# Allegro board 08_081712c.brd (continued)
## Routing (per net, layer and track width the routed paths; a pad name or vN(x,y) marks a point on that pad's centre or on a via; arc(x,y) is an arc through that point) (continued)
JTAG_EMU*: length 28
  TOP w0.14: R475.2 v1(206.36,16.31)
  L3_SIG w0.114: v1(190.25,32.07) 191.39,30.92 195.58,30.92 203.07,23.43 203.07,20.51 204.34,19.24 204.98,19.24 205.31,18.91 v2(206.65,18.91)
  BOTTOM w0.14: v2(206.65,18.91) 206.65,16.59 v1(206.36,16.31) ; R500.1 v1(190.25,32.07)
JTAG_EMU_CONN*: length 27.1
  TOP w0.14: R488.2 S11.8 195.71,58.61 194.94,57.85 194.94,57.12 195.71,56.36 195.71,54.67 193.04,52.01 193.04,45.15 189.99,42.1 189.99,40.45 v1(190.37,40.07)
  BOTTOM w0.14: v1(190.37,40.07) 190.88,40.07 191.27,39.68 U60.11
JTAG_EN: length 61.5
  TOP w0.14: U58.14 U58.15 213.38,36.24 212.98,36.64 212.28,36.64 R496.1 v1(210.47,37.46)
  TOP w0.203: v1(220.47,20.38) 220.16,20.69 U59.2
  L3_SIG w0.114: v1(193.04,40.32) 207.14,40.32 209.99,37.46 v1(210.47,37.46)
  L8_SIG w0.114: v1(220.47,20.38) 220.01,19.93 218.14,19.93 215.58,22.48 213.35,22.48 210.16,19.29 209.63,19.29 209.42,19.49 209.42,19.72 209.15,20 208.76,20 v2(208.64,20.11)
  BOTTOM w0.114: U60.15 193.27,40.09 v1(193.04,40.32)
  BOTTOM w0.127: v2(208.64,20.11) 208.64,21.7 209.35,22.4 209.35,24.19 209.67,24.51 210.81,24.51 211.82,25.53 211.82,36.11 v1(210.47,37.46)
  BOTTOM w0.14: v1(193.04,40.32) 192.77,40.06 U60.14
JTAG_IO: length 10
  TOP w0.203: C368.1 211.72,34.6 U58.16 ; C366.1 220.44,23.94 220.16,23.66 U59.6
  TOP w0.508: C366.1 v1(220.48,24.8) ; P10.2 v1(227.21,21.65) ; R488.1 v1(195.71,64.08) ; C368.1 v1(210.67,34.87) ; R490.1 v1(198.25,47.56)
  BOTTOM w0.203: C365.1 194.93,38.03 U60.16
  BOTTOM w0.508: C365.1 v1(195.91,38.3)
JTAG_PD: length 24.4
  L3_SIG w0.114: v2(209.05,20.51) 208.66,20.89 208.24,20.89 207.1,19.75 204.6,19.75 203.83,20.51 203.83,23.43 194.82,32.45 193.67,32.45 v1(193.29,32.07)
  BOTTOM w0.14: R501.1 v1(193.29,32.07)
JTAG_PD_CONN: length 27
  TOP w0.14: v1(192.27,40.96) 194.18,42.86 209.55,42.86 213.49,46.8 R489.2
  BOTTOM w0.14: U60.13 v1(192.27,40.96)
JTAG_SOM_ROUTE: length 21.4
  TOP w0.127: U15.1 232.29,83.41 230.12,85.58 S2.2 230.12,95.85 232.28,98.02 U14.1
JTAG_SPI_CS_N: length 5.9
  L8_SIG w0.114: v2(207.05,18.91) 206.77,18.64 205.73,18.64 205.17,19.2 205.17,19.45 206.63,20.91 206.63,21.69 v2(207.05,22.11)
JTAG_TARGET_RESET_N: length 14.5
  TOP w0.203: U59.9 v1(217.93,21.91) ; U59.8 218.67,22.31 v1(218.31,22.67)
  L8_SIG w0.114: v1(218.31,22.67) 218.31,22.29 v1(217.93,21.91) 216.6,23.24 212.21,23.24 209.2,20.24 208.93,20.24 208.66,20.51 v2(208.24,20.51)
JTAG_TARGET_RESET_N_CONN: length 45.4
  TOP w0.14: S11.10 v1(198.25,50.16) R490.2 R491.1
  TOP w0.203: U59.4 v1(222,21.91) ; U59.5 221.38,22.31 v1(221.74,22.67)
  L3_SIG w0.114: v1(221.74,22.67) 221.74,22.16 v1(222,21.91)
  BOTTOM w0.127: v1(221.74,22.67) 219.96,24.45 219.96,31.78 212.39,39.34 209.06,39.34 v1(198.25,50.16)
JTAG_TARGET_RESET_SOM_A*: length 98.1
  TOP w0.127: SOMA.146 v1(150.39,74.95)
  TOP w0.14: U15.6 v1(233.32,80.91)
  L8_SIG w0.127: v1(163.04,71.2) 163.04,72.24 161.04,74.24 150.67,74.24 150.39,74.52 v1(150.39,74.95)
  BOTTOM w0.127: v1(163.04,71.2) 164.59,72.75 194,72.75 196.9,75.64 196.9,78.97 198.88,80.95 211,80.95 215.26,85.22 229.54,85.22 233.32,81.43 v1(233.32,80.91)
JTAG_TARGET_RESET_SOM_B*: length 50.2
  TOP w0.127: SOMB.146 v1(277.39,74.95)
  TOP w0.14: v1(235.81,80.92) 235.33,81.41 U15.5
  BOTTOM w0.127: v1(277.39,74.95) 274.1,71.65 262.46,71.65 261.04,73.08 249.2,73.08 240.49,81.79 238.38,81.79 237.52,80.92 v1(235.81,80.92)
JTAG_TCK: length 23.8
  TOP w0.14: R474.2 v1(205.49,27.67) ; v1(214.88,31.31) U58.5
  L8_SIG w0.114: v2(206.65,19.31) 206.65,19.72 208.41,21.49 208.41,22.77 205.49,25.7 v1(205.49,27.67) 207.53,29.72 213.29,29.72 v1(214.88,31.31)
JTAG_TCK_CONN: length 24.2
  TOP w0.14: S11.13 v1(205.87,50.03)
  TOP w0.203: R494.2 v1(214.38,40.12)
  L8_SIG w0.14: v1(214.38,40.12) 213.53,39.27 211.11,39.27 205.87,44.51 205.87,46.5 205.62,46.75 204.46,46.75 204.22,46.99 204.22,47.34 204.46,47.58 205.62,47.58 205.87,47.83 205.87,48.18 205.62,48.42 204.46,48.42 204.22,48.67 204.22,49.01 204.46,49.26 205.62,49.26 205.87,49.51 v1(205.87,50.03)
JTAG_TCK_SOM_A: length 103
  TOP w0.127: SOMA.138 v1(148.39,74.95)
  TOP w0.14: U14.13 237.79,96.52 v1(237.31,96.99) ; U9.5 v1(202.73,86.73)
  L8_SIG w0.127: v1(202.73,86.73) 193.65,77.65 154.77,77.65 153.54,76.43 149.26,76.43 148.46,75.63 148.46,75.59 148.39,75.52 v1(148.39,74.95)
  BOTTOM w0.127: v1(237.31,96.99) 236.44,96.99 234.44,95 234.44,94.36 233.93,93.85 211.94,93.85 206.22,88.14 204.14,88.14 v1(202.73,86.73)
JTAG_TCK_SOM_B: length 93.8
  TOP w0.127: SOMB.138 v1(275.39,75.71)
  TOP w0.14: U14.14 239.05,97.02 v1(239.45,96.62) ; U9.6 v1(205.54,86.08)
  BOTTOM w0.127: v1(205.54,86.08) 206.38,86.92 206.38,87.5 212.09,93.22 233.93,93.22 234.95,94.23 234.95,95 236.44,96.49 237.74,96.49 238.09,96.14 238.96,96.14 v1(239.45,96.62) 240.56,96.62 251.36,85.83 256.67,85.83 261.85,80.65 261.85,75.08 263.4,73.53 271.98,73.53 274.16,75.71 v1(275.39,75.71)
JTAG_TDI: length 22.7
  TOP w0.14: U58.6 215.38,31.95 v1(215.77,31.56)
  L8_SIG w0.114: v2(207.84,20.11) 207.84,20.5 209.17,21.82 209.17,22.5 206.22,25.44 206.22,27.66 207.52,28.96 214.12,28.96 215.77,30.61 v1(215.77,31.56)
JTAG_TDI_CONN: length 24
  TOP w0.14: S11.11 v1(200.79,50.03)
  TOP w0.203: R493.2 v1(215.9,40.12)
  L8_SIG w0.14: v1(215.9,40.12) 213.95,38.16 210.95,38.16 200.79,48.32 v1(200.79,50.03)
JTAG_TDI_SOM_A: length 107.1
  TOP w0.127: SOMA.142 v1(149.39,74.95)
  TOP w0.14: U14.10 v1(239.3,95.02)
  L8_SIG w0.127: v1(162.05,72.03) 160.47,73.61 150.16,73.61 149.39,74.38 v1(149.39,74.95)
  BOTTOM w0.127: v1(162.05,72.03) 163.86,73.84 175.52,73.84 178.77,77.09 184.33,77.09 186.66,74.75 192.66,74.75 194.31,76.4 194.31,79.63 198.68,84 204.77,84 209.96,89.18 233.46,89.18 v1(239.3,95.02)
JTAG_TDI_SOM_B: length 55
  TOP w0.127: SOMB.142 v1(276.39,75.71)
  TOP w0.14: U52.7 v1(235.78,87.52)
  BOTTOM w0.127: v1(235.78,87.52) 236.84,86.46 241.43,86.46 242.75,85.14 256.57,85.14 260.99,80.72 260.99,74.8 263.14,72.64 273.85,72.64 276.39,75.19 v1(276.39,75.71)
JTAG_TDI_SOM_B_Z: length 19.4
  TOP w0.127: U52.6 236.03,88.02 237.69,86.36 240.92,86.36 243.05,88.49 243.05,91.97 239.51,95.52 U14.11
JTAG_TDI_TDO_SOM_B: length 3
  TOP w0.127: U52.2 234.07,90.02 233.94,89.9 233.94,88.67 234.09,88.52 U52.5
JTAG_TDO: length 24.6
  L3_SIG w0.114: v1(191.77,32.07) 191.77,33.21 192.34,33.78 192.34,34.34 192.51,34.5 192.75,34.5 192.91,34.34 192.91,33.78 193.08,33.61 193.32,33.61 193.48,33.78 193.48,34.34 193.65,34.5 193.89,34.5 194.06,34.34 194.06,33.78 194.25,33.59 194.69,33.59 204.6,23.69 204.6,22.67 205.56,21.71 v2(205.84,21.71)
  BOTTOM w0.14: R499.1 v1(191.77,32.07)
JTAG_TDO_CONN: length 27.1
  TOP w0.14: S11.12 203.33,49.34 204.22,48.45 205.23,48.45 205.99,47.69 205.99,44.89 205.23,44.13 193.67,44.13 191.26,41.72 v1(191.26,40.7)
  BOTTOM w0.14: U60.12 191.77,39.76 191.77,39.77 191.77,40.2 v1(191.26,40.7)
JTAG_TDO_SOM_A: length 103.6
  TOP w0.127: SOMA.140 v1(148.9,75.45)
  TOP w0.14: U52.4 v1(235.65,89.02)
  L8_SIG w0.127: v1(148.9,75.45) 148.9,74.17 149.96,73.11 160.15,73.11 v1(162.05,71.2)
  BOTTOM w0.127: v1(235.65,89.02) 234.77,88.14 224.79,88.14 224.15,88.77 210.31,88.77 204.98,83.44 199.29,83.44 195.07,79.22 195.07,76.25 193.14,74.32 186.13,74.32 183.9,76.56 179.1,76.56 175.82,73.28 164.13,73.28 v1(162.05,71.2)
JTAG_TDO_SOM_A_Z: length 20.8
  TOP w0.127: U14.6 235.98,95.52 236.4,95.1 236.4,93.73 236.75,93.37 240.26,93.37 242.29,91.34 242.29,89.2 241.11,88.02 U52.11 237.74,88.02 236.24,89.52 U52.3
JTAG_TDO_SOM_B: length 51.2
  TOP w0.127: SOMB.140 v1(275.9,76.22)
  TOP w0.14: U52.9 v1(239.43,87.02)
  BOTTOM w0.127: v1(239.43,87.02) 241.26,87.02 242.86,85.42 256.68,85.42 261.39,80.71 261.39,74.9 263.3,73 273.41,73 275.9,75.49 v1(275.9,76.22)
JTAG_TDO_SOM_B_Z: length 18
  TOP w0.127: U52.10 241.32,87.52 242.65,88.85 242.65,91.54 240.54,93.65 237.08,93.65 236.85,93.88 236.85,95.25 236.09,96.02 U14.5
JTAG_TMS: length 22.9
  TOP w0.14: U58.4 214.38,32.2 v1(213.99,31.81)
  L8_SIG w0.114: v2(205.84,22.11) 206.25,22.51 206.25,23.18 204.72,24.7 204.72,27.94 208.6,31.81 210.66,31.81 210.86,31.61 210.86,30.78 211.06,30.58 211.35,30.58 211.55,30.78 211.55,31.61 211.75,31.81 212.03,31.81 212.23,31.61 212.23,30.78 212.43,30.58 212.72,30.58 212.92,30.78 212.92,31.61 213.12,31.81 v1(213.99,31.81)
JTAG_TMS_CONN: length 24.2
  TOP w0.14: S11.14 v1(208.41,50.03)
  TOP w0.203: R492.2 v1(212.85,40.12)
  L8_SIG w0.14: v1(208.41,50.03) 208.41,49.32 208.16,49.07 207.26,49.07 207.01,48.83 207.01,48.48 207.26,48.24 209.43,48.24 209.68,47.99 209.68,47.64 209.43,47.4 207.26,47.4 207.01,47.15 207.01,46.81 207.26,46.56 209.43,46.56 209.68,46.31 209.68,45.97 209.43,45.72 208.4,45.72 208.15,45.48 208.15,43.62 211.66,40.12 v1(212.85,40.12)
JTAG_TMS_SOM_A: length 102
  TOP w0.127: SOMA.136 v1(147.9,75.45)
  TOP w0.14: U9.2 203.11,88.68 v1(202.82,88.39) ; U14.3 v1(235.78,97.02)
  L8_SIG w0.127: v1(202.82,88.39) 202.82,87.63 193.29,78.1 154.48,78.1 153.16,76.78 148.69,76.78 147.9,75.99 v1(147.9,75.45)
  BOTTOM w0.127: v1(202.82,88.39) 203.11,88.68 205.97,88.68 211.69,94.4 232.48,94.4 235.09,97.02 v1(235.78,97.02)
JTAG_TMS_SOM_B: length 97
  TOP w0.127: SOMB.136 v1(274.9,76.22)
  TOP w0.14: U9.3 203.22,88.03 202.95,87.76 v1(202.13,87.76) ; U14.2 v1(233.77,97.52)
  BOTTOM w0.127: v1(202.13,87.76) 202.13,88.62 202.79,89.28 205.79,89.28 211.58,95.07 231.33,95.07 v1(233.77,97.52) 240.69,97.52 251.92,86.28 256.61,86.28 262.31,80.59 262.31,75.13 263.47,73.96 271.75,73.96 274.01,76.22 v1(274.9,76.22)
JTAG_TRST_N: length 22.7
  TOP w0.14: v1(216.41,31.94) 215.88,32.47 U58.7
  L8_SIG w0.114: v1(216.41,31.94) 216.41,31.24 216.61,31.04 217.73,31.04 217.93,30.84 217.93,30.56 217.73,30.36 216.61,30.36 216.41,30.16 216.41,25.59 215.9,25.08 209.23,25.08 208.91,24.76 208.91,24.07 209.93,23.05 209.93,21.8 v2(209.05,20.91)
JTAG_TRST_N_CONN: length 24.1
  TOP w0.14: S11.15 v1(210.95,50.03)
  TOP w0.203: R495.2 v1(217.42,40.12)
  L8_SIG w0.14: v1(210.95,50.03) 210.95,49.28 211.19,49.03 212.1,49.03 212.34,48.79 212.34,48.44 212.1,48.19 211.19,48.19 210.95,47.95 210.95,47.6 211.19,47.35 212.1,47.35 212.34,47.11 212.34,46.76 212.1,46.52 211.19,46.52 210.95,46.27 210.95,45.92 211.19,45.68 212.1,45.68 212.34,45.43 212.34,45.09 212.1,44.84 211.19,44.84 210.95,44.59 210.95,42.1 211.96,41.08 216.46,41.08 v1(217.42,40.12)
JTAG_TRST_SOM_A*: length 96.8
  TOP w0.127: SOMA.144 v1(149.9,75.45)
  TOP w0.14: U15.3 v1(235.78,82.41) ; U9.9 v1(208.58,86.08)
  L8_SIG w0.127: v1(149.9,75.45) 150.49,76.05 153.75,76.05 154.79,77.09 193.62,77.09 200.99,84.45 206.96,84.45 v1(208.58,86.08)
  BOTTOM w0.127: v1(208.58,86.08) 212.19,86.08 213.11,86.99 230.63,86.99 235.22,82.41 v1(235.78,82.41)
JTAG_TRST_SOM_B*: length 79.9
  TOP w0.127: SOMB.144 v1(276.9,76.22)
  TOP w0.14: U9.8 v1(211.29,85.43) ; U15.2 v1(233.77,82.91)
  BOTTOM w0.127: v1(276.9,76.22) 276.9,75.14 273.89,72.14 262.76,72.14 261.37,73.53 249.48,73.53 240.63,82.38 237.19,82.38 236.69,81.88 234.8,81.88 v1(233.77,82.91) 230.1,86.59 213.79,86.59 212.63,85.43 v1(211.29,85.43)
JTG0_TARGET_RESET*: length 53.2
  TOP w0.127: v1(206.76,73.86) 209.67,73.86 216.22,80.41 U15.7
  TOP w0.14: S11.7 v1(198.25,61.47) 200.46,63.69 R532.1 ; R583.2 v1(206.76,73.86)
  BOTTOM w0.14: v1(198.25,61.47) 198.25,65.35 v1(206.76,73.86)
JTG0_TCK/SWCLK_LOCAL: length 89.4
  TOP w0.14: S11.4 v1(205.87,61.47) 206.5,62.11 P8.4 ; U14.12 v1(237.55,96.02)
  L8_SIG w0.127: v1(205.87,61.47) 204.34,61.47 203.93,61.07 203.93,60.48 204.44,59.97 208.48,59.97 214.3,65.79 214.3,73.97 216.74,76.41 216.74,79.46 219.79,82.5 219.79,88.27 226.77,95.25 234.57,95.25 235.35,94.47 236.01,94.47 237.55,96.01 v1(237.55,96.02)
  BOTTOM w0.14: P35.4 211.24,76.38 211.24,65.73 207.93,62.42 206.81,62.42 v1(205.87,61.47)
JTG0_TDI_LOCAL: length 95.6
  TOP w0.14: U14.9 v1(237.55,94.52) ; S11.6 v1(200.79,61.47) 201.73,62.42 203.07,62.42 203.96,63.31 P8.8
  L8_SIG w0.127: v1(237.55,94.52) 236.91,93.88 225.95,93.88 220.14,88.07 220.14,82.36 217.09,79.31 217.09,76.27 214.66,73.83 214.66,65.41 208.73,59.49 202.77,59.49 v1(200.79,61.47)
  BOTTOM w0.14: P35.8 210.13,74.96 210.13,66.3 207.64,63.82 203.13,63.82 v1(200.79,61.47)
JTG0_TDO_LOCAL: length 91.8
  TOP w0.14: P8.6 205.23,63.38 v1(203.33,61.47) S11.5 ; U14.7 v1(235.78,95.02)
  L8_SIG w0.127: v1(203.33,61.47) 203.33,62.61 203.71,62.99 204.47,62.99 204.65,62.81 204.65,62.42 204.84,62.23 205.1,62.23 205.29,62.42 205.29,62.81 205.47,62.99 206.38,62.99 206.76,62.61 206.76,60.94 207.24,60.45 208.25,60.45 213.94,66.15 213.94,74.12 216.38,76.56 216.38,79.6 219.43,82.65 219.43,88.42 226.87,95.86 234.94,95.86 v1(235.78,95.02)
  BOTTOM w0.14: P35.6 210.69,75.66 210.69,66.04 207.71,63.06 204.91,63.06 v1(203.33,61.47)
JTG0_TMS/SWDIO_LOCAL: length 87.6
  TOP w0.14: U14.4 v1(233.77,96.52) ; S11.3 v1(208.41,61.47) 207.77,62.11 P8.2
  L8_SIG w0.127: v1(208.41,61.47) 209,62.07 209,62.33 208.25,63.08 208.25,63.34 208.44,63.53 208.7,63.53 209.45,62.78 209.71,62.78 209.9,62.97 209.9,63.23 209.15,63.98 209.15,64.24 209.34,64.43 209.6,64.43 210.35,63.68 210.61,63.68 210.8,63.86 210.8,64.13 210.05,64.88 210.05,65.14 210.23,65.33 210.5,65.33 211.25,64.58 211.51,64.58 211.7,64.76 211.7,65.03 210.95,65.78 210.95,66.04 211.13,66.22 211.39,66.22 212.14,65.47 212.41,65.47 212.59,65.66 212.59,65.92 211.84,66.67 211.84,66.94 212.03,67.12 212.29,67.12 213.04,66.37 213.31,66.37 213.59,66.66 213.59,74.27 216.03,76.71 216.03,79.76 219.07,82.8 219.07,88.56 227.28,96.77 233.52,96.77 v1(233.77,96.52)
  BOTTOM w0.14: P35.2 211.79,77.11 211.79,65.48 208.41,62.1 v1(208.41,61.47)
JTG0_TRST_LOCAL*: length 73.2
  TOP w0.127: U15.4 236.15,81.91 236.37,81.69 236.37,80.11 235.69,79.43 216.56,79.43 210.06,72.92 204.98,72.92 204.63,73.27 R584.2 ; 203.68,73.86 202.7,72.88 R523.1
  TOP w0.14: S11.2 210.95,58.99 210.31,58.36 197.61,58.36 196.85,59.12 196.85,61.79 P8.9 202.7,67.64 R528.2 R523.1 ; 203.68,73.86 R584.2
LED_BLUE: length 5.4
  TOP w0.14: U54.G13 202.06,20.51 201.3,19.75 R478.1
LED_GREEN: length 5.7
  TOP w0.14: U54.D13 202.76,19.31 201.42,17.97 R476.1
LED_RED: length 16.1
  TOP w0.14: R477.1 v1(189.36,18.86) ; U54.E13 202.15,19.71 201.29,18.86 v1(197.99,18.86)
  BOTTOM w0.14: v1(197.99,18.86) v1(189.36,18.86)
LINKPORT0_ACK_SOM_A: length 70.8
  TOP w0.127: SOMA.255 v1(177.65,64.78) ; R377.1 v1(228.22,43.81)
  BOTTOM w0.127: v1(228.22,43.81) 228.22,47.24 227.77,47.69 215.9,47.69 210.14,53.46 178.57,53.46 176.91,55.12 176.91,63.37 177.61,64.08 177.61,64.75 v1(177.65,64.78)
LINKPORT0_ACK_SOM_B: length 116.9
  TOP w0.127: SOMB.255 v1(304.65,69.27) ; R393.2 v1(228.22,33.28)
  BOTTOM w0.127: v1(228.22,33.28) 233.2,38.26 238.48,38.26 243.58,43.35 243.58,46.49 239.77,50.3 239.77,66.45 243.73,70.41 296.21,70.41 298.45,68.16 304.28,68.16 304.65,68.53 v1(304.65,69.27)
LINKPORT0_CLK_SOM_A: length 70.4
  TOP w0.127: SOMA.253 v1(177.14,64.27) ; R376.1 v1(227.08,43.81)
  BOTTOM w0.127: v1(177.14,64.27) 176.4,63.53 176.4,54.36 177.8,52.96 209.93,52.96 215.7,47.19 226.75,47.19 227.08,46.86 v1(227.08,43.81)
LINKPORT0_CLK_SOM_B: length 116.8
  TOP w0.127: R392.2 v1(227.08,33.28) ; SOMB.253 v1(304.14,68.76)
  BOTTOM w0.127: v1(304.14,68.76) 298.56,68.76 296.42,70.91 243.52,70.91 239.27,66.65 239.27,50.09 243.08,46.28 243.08,43.56 238.28,38.76 231.8,38.76 227.08,34.04 v1(227.08,33.28)
LINKPORT0_D0_SOM_A: length 70.7
  TOP w0.127: SOMA.257 v1(178.14,64.27) ; R372.1 v1(230.12,43.81)
  BOTTOM w0.127: v1(178.14,64.27) 178.14,55.28 179.47,53.96 210.35,53.96 216.11,48.19 228.54,48.19 230.12,46.61 v1(230.12,43.81)
LINKPORT0_D0_SOM_B: length 116.5
  TOP w0.127: SOMB.257 v1(305.14,68.76) ; R388.2 v1(230.12,33.28)
  BOTTOM w0.127: v1(230.12,33.28) 230.12,34.52 233.36,37.76 239.96,37.76 244.22,42.02 244.22,46.55 240.27,50.51 240.27,66.24 243.94,69.91 244.06,69.91 244.07,69.91 296.03,69.91 298.28,67.66 305.02,67.66 305.14,67.79 v1(305.14,68.76)
LINKPORT0_D1_SOM_A: length 70.4
  TOP w0.127: SOMA.259 v1(178.65,64.78) ; R373.1 v1(231.27,43.81)
  BOTTOM w0.127: v1(231.27,43.81) 231.27,46.36 228.93,48.69 216.32,48.69 210.55,54.46 180.75,54.46 178.65,56.56 v1(178.65,64.78)
LINKPORT0_D1_SOM_B: length 116.5
  TOP w0.127: SOMB.259 v1(305.65,69.27) ; R389.2 v1(231.27,33.28)
  BOTTOM w0.127: v1(305.65,69.27) 305.65,67.39 305.41,67.16 298.12,67.16 295.83,69.44 244.27,69.44 244.23,69.41 244.14,69.41 240.77,66.03 240.77,50.71 244.86,46.63 244.86,41.95 240.17,37.26 235.24,37.26 v1(231.27,33.28)
LINKPORT0_D2_SOM_A: length 70.4
  TOP w0.127: SOMA.261 v1(179.14,64.27) ; R374.1 v1(232.41,43.81)
  BOTTOM w0.127: v1(179.14,64.27) 179.14,57.46 181.64,54.96 210.76,54.96 216.53,49.19 229.32,49.19 232.41,46.1 v1(232.41,43.81)
LINKPORT0_D2_SOM_B: length 116.5
  TOP w0.127: R390.2 v1(232.41,33.28) ; SOMB.261 v1(306.14,68.76)
  BOTTOM w0.127: v1(232.41,33.28) 233.1,33.98 233.1,34.45 233.55,34.9 234.03,34.9 234.51,34.9 234.96,35.35 234.96,35.83 235.89,36.76 240.37,36.76 246.25,42.64 246.25,45.94 241.27,50.92 241.27,65.82 244.38,68.94 244.42,68.94 244.46,68.97 295.6,68.97 295.66,68.91 295.67,68.91 297.92,66.66 305.93,66.66 306.14,66.88 v1(306.14,68.76)
LINKPORT0_D3_SOM_A: length 70.4
  TOP w0.127: R375.1 v1(233.55,43.81) ; SOMA.263 v1(179.65,64.78)
  BOTTOM w0.127: v1(179.65,64.78) 179.65,58.61 182.79,55.46 210.97,55.46 216.73,49.69 229.71,49.69 233.81,45.59 233.81,44.06 v1(233.55,43.81)
LINKPORT0_D3_SOM_B: length 116.5
  TOP w0.127: SOMB.263 v1(306.65,69.27) ; R391.2 v1(233.55,33.28)
  BOTTOM w0.127: v1(306.65,69.27) 306.65,66.49 306.35,66.19 297.72,66.19 295.48,68.44 295.47,68.44 295.4,68.5 244.66,68.5 241.77,65.62 241.77,51.13 246.74,46.15 246.74,42.42 240.58,36.26 236.53,36.26 v1(233.55,33.28)
LINKPORT1_ACK_SOM_A: length 70.4
  TOP w0.127: R383.1 v1(236.6,43.81) ; SOMA.269 v1(181.14,64.27)
  BOTTOM w0.127: v1(236.6,43.81) 236.6,44.96 230.85,50.71 217.13,50.71 210.88,56.96 184.21,56.96 181.14,60.03 v1(181.14,64.27)
LINKPORT1_ACK_SOM_B: length 116.6
  TOP w0.127: SOMB.269 v1(308.14,68.76) ; R399.2 v1(236.6,33.28)
  BOTTOM w0.127: v1(236.6,33.28) 237.93,34.61 239.77,34.61 240.48,35.32 244.49,35.32 247.71,38.54 247.71,46.67 242.76,51.62 242.76,65.25 244.98,67.47 295.08,67.47 297.42,65.12 307.69,65.12 308.14,65.58 v1(308.14,68.76)
LINKPORT1_CLK_SOM_A: length 70.6
  TOP w0.127: R382.1 v1(235.46,43.81) ; SOMA.267 v1(180.65,64.78)
  BOTTOM w0.127: v1(180.65,64.78) 180.65,58.5 183.21,55.93 211.16,55.93 216.88,50.22 230.07,50.22 235.46,44.83 v1(235.46,43.81)
LINKPORT1_CLK_SOM_B: length 116.6
  TOP w0.127: R398.2 v1(235.46,33.28) ; SOMB.267 v1(307.65,69.27)
  BOTTOM w0.127: v1(307.65,69.27) 307.65,66.6 306.66,65.62 297.63,65.62 295.28,67.97 244.78,67.97 242.26,65.44 242.26,51.41 247.21,46.46 247.21,40.55 242.45,35.79 240.29,35.79 239.61,35.11 237.28,35.11 v1(235.46,33.28)
LINKPORT1_D0_SOM_A: length 70.4
  TOP w0.127: SOMA.271 v1(181.65,64.78) ; R378.1 v1(238.63,43.81)
  BOTTOM w0.127: v1(238.63,43.81) 238.63,44.96 232.38,51.21 217.33,51.21 211.08,57.46 186.89,57.46 181.65,62.7 v1(181.65,64.78)
LINKPORT1_D0_SOM_B: length 116.6
  TOP w0.127: SOMB.271 v1(308.65,69.27) ; R394.2 v1(238.63,33.28)
  BOTTOM w0.127: v1(308.65,69.27) 308.65,65.31 307.95,64.62 297.22,64.62 294.87,66.97 245.19,66.97 243.23,65.01 243.23,51.86 248.21,46.88 248.21,37.77 245.29,34.85 240.68,34.85 239.87,34.04 239.39,34.04 v1(238.63,33.28)
LINKPORT1_D1_SOM_A: length 70.3
  TOP w0.127: R379.1 v1(239.78,43.81) ; SOMA.273 v1(182.14,64.27)
  BOTTOM w0.127: v1(182.14,64.27) 182.14,63.47 187.66,57.96 211.29,57.96 217.54,51.71 232.64,51.71 239.78,44.58 v1(239.78,43.81)
LINKPORT1_D1_SOM_B: length 116.6
  TOP w0.127: R395.2 v1(239.78,33.28) ; SOMB.273 v1(309.14,68.76)
  BOTTOM w0.127: v1(309.14,68.76) 309.14,64.54 308.72,64.12 297.01,64.12 294.66,66.47 245.39,66.47 243.76,64.83 243.76,52.04 248.71,47.08 248.71,36.75 245.72,33.75 245.14,33.75 244.86,34.04 244.15,34.04 243.86,33.75 243.26,33.75 242.64,34.38 240.87,34.38 v1(239.78,33.28)
LINKPORT1_D2_SOM_A: length 70.4
  TOP w0.127: SOMA.275 v1(182.65,64.78) ; R380.1 v1(240.92,43.81)
  BOTTOM w0.127: v1(182.65,64.78) 182.65,64.06 188.25,58.46 211.5,58.46 217.75,52.21 232.9,52.21 240.92,44.2 v1(240.92,43.81)
LINKPORT1_D2_SOM_B: length 117
  TOP w0.127: R396.2 v1(240.92,33.28) ; SOMB.275 v1(309.65,69.27)
  BOTTOM w0.127: v1(240.92,33.28) 241.55,33.91 242.44,33.91 243.07,33.28 245.91,33.28 249.21,36.59 249.21,47.29 244.26,52.24 244.26,64.63 245.6,65.97 294.45,65.97 296.8,63.62 309.21,63.62 309.65,64.06 v1(309.65,69.27)
LINKPORT1_D3_SOM_A: length 70.7
  TOP w0.127: SOMA.277 v1(183.14,64.27) ; R381.1 v1(242.06,43.81)
  BOTTOM w0.127: v1(242.06,43.81) 233.16,52.71 217.96,52.71 211.71,58.96 188.46,58.96 v1(183.14,64.27)
LINKPORT1_D3_SOM_B: length 116.5
  TOP w0.127: R397.2 v1(242.06,33.28) ; SOMB.277 v1(310.14,68.76)
  BOTTOM w0.127: v1(242.06,33.28) 242.96,32.38 247.14,32.38 249.81,35.05 249.81,47.4 244.76,52.45 244.76,64.42 245.81,65.47 294.25,65.47 296.6,63.12 309.37,63.12 310.14,63.89 v1(310.14,68.76)
MDI_0_N: length 19.9
  BOTTOM w0.127: U1.13 137.77,39.99 arc(137.78,39.95) 137.8,39.92 arc(137.83,39.89) 137.83,39.85 137.83,38.13 arc(138.1,36.79) 138.86,35.65 arc(139.34,34.93) 139.51,34.09 139.51,31.11 arc(139.59,30.92) 139.77,30.85 D1.3 140.83,30.85 arc(141.04,30.76) 141.13,30.55 141.13,25.88 arc(141.1,25.73) 141.01,25.59 140.61,25.2 arc(140.37,25.03) 140.08,24.98 140.08,24.98 arc(139.73,24.91) 139.42,24.71 P1.10
MDI_0_N_A: length 19.9
  BOTTOM w0.127: U2.13 264.77,39.99 arc(264.78,39.95) 264.8,39.92 arc(264.83,39.89) 264.83,39.85 264.83,38.13 arc(265.1,36.79) 265.86,35.65 arc(266.34,34.93) 266.51,34.09 266.51,31.11 arc(266.59,30.92) 266.77,30.85 D3.3 267.83,30.85 arc(268.04,30.76) 268.13,30.55 268.13,25.88 arc(268.1,25.73) 268.01,25.59 267.61,25.2 arc(267.37,25.03) 267.08,24.98 267.08,24.98 arc(266.73,24.91) 266.42,24.71 P2.10
MDI_0_P: length 18.8
  BOTTOM w0.127: U1.12 138.28,39.99 arc(138.27,39.95) 138.25,39.92 arc(138.22,39.89) 138.22,39.85 138.22,38.13 arc(138.45,36.93) 139.13,35.92 arc(139.69,35.08) 139.89,34.09 139.89,33.07 arc(139.98,32.85) 140.21,32.75 D1.1 141.18,32.75 arc(141.41,32.66) 141.51,32.42 141.51,25.88 arc(141.45,25.58) 141.28,25.33 140.63,24.68 arc(140.6,24.63) 140.59,24.57 P1.11
MDI_0_P_A: length 18.8
  BOTTOM w0.127: U2.12 265.28,39.99 arc(265.27,39.95) 265.25,39.92 arc(265.22,39.89) 265.22,39.85 265.22,38.13 arc(265.45,36.93) 266.13,35.92 arc(266.69,35.08) 266.89,34.09 266.89,33.07 arc(266.98,32.85) 267.21,32.75 D3.1 268.18,32.75 arc(268.41,32.66) 268.51,32.42 268.51,25.88 arc(268.45,25.58) 268.28,25.33 267.63,24.68 arc(267.6,24.63) 267.59,24.57 P2.11
MDI_1_N: length 25.2
  BOTTOM w0.127: U1.15 136.77,39.99 arc(136.78,39.95) 136.8,39.92 arc(136.83,39.89) 136.83,39.85 136.83,37.98 arc(137.17,36.32) 138.11,34.9 arc(138.39,34.48) 138.49,33.98 138.49,33.1 arc(138.39,32.85) 138.15,32.75 D1.6 137.21,32.75 arc(136.97,32.66) 136.88,32.42 136.88,22.7 arc(136.83,22.46) 136.69,22.26 arc(136.57,22.08) 136.53,21.87 136.53,21.21 arc(136.82,20.51) 137.52,20.22 arc(138.42,20.4) 139.18,20.9 P1.5
MDI_1_N_A: length 25.2
  BOTTOM w0.127: U2.15 263.77,39.99 arc(263.78,39.95) 263.8,39.92 arc(263.83,39.89) 263.83,39.85 263.83,37.98 arc(264.17,36.32) 265.11,34.9 arc(265.39,34.48) 265.49,33.98 265.49,33.1 arc(265.39,32.85) 265.15,32.75 D3.6 264.21,32.75 arc(263.97,32.66) 263.88,32.42 263.88,22.7 arc(263.83,22.46) 263.69,22.26 arc(263.57,22.08) 263.53,21.87 263.53,21.21 arc(263.82,20.51) 264.52,20.22 arc(265.42,20.4) 266.18,20.9 P2.5
MDI_1_P: length 21.1
  BOTTOM w0.127: P1.4 137.54,22.01 arc(137.5,22.21) 137.39,22.38 137.38,22.39 arc(137.29,22.52) 137.26,22.68 arc(137.26,22.69) 137.26,22.7 137.26,30.55 arc(137.35,30.76) 137.56,30.85 D1.4 138.61,30.85 arc(138.8,30.93) 138.87,31.12 138.87,33.98 arc(138.75,34.62) 138.38,35.17 arc(137.52,36.46) 137.22,37.98 137.22,39.85 arc(137.22,39.89) 137.25,39.92 arc(137.27,39.95) 137.28,39.99 U1.14
MDI_1_P_A: length 21.1
  BOTTOM w0.127: 264.28,40.54 264.28,39.99 arc(264.27,39.95) 264.25,39.92 arc(264.22,39.89) 264.22,39.85 264.22,37.98 arc(264.52,36.46) 265.38,35.17 arc(265.75,34.62) 265.87,33.98 265.87,31.12 arc(265.8,30.93) 265.61,30.85 D3.4 264.56,30.85 arc(264.35,30.76) 264.26,30.55 264.26,22.7 arc(264.26,22.69) 264.26,22.68 arc(264.29,22.52) 264.38,22.39 264.39,22.38 arc(264.5,22.21) 264.54,22.01 P2.4
MDI_2_N: length 22.3
  BOTTOM w0.127: P1.2 134.27,22.08 arc(134.51,22.24) 134.79,22.3 134.81,22.3 arc(134.99,22.33) 135.16,22.4 135.2,22.43 arc(135.25,22.46) 135.29,22.51 135.67,22.89 arc(135.76,23.02) 135.79,23.18 135.79,30.55 arc(135.7,30.76) 135.49,30.85 D2.3 134.44,30.85 arc(134.25,30.93) 134.18,31.12 134.18,33.98 arc(134.3,34.62) 134.67,35.17 arc(135.53,36.46) 135.83,37.98 135.83,39.85 arc(135.83,39.89) 135.8,39.92 arc(135.78,39.95) 135.77,39.99 U1.17
MDI_2_N_A: length 22.3
  BOTTOM w0.127: P2.2 261.27,22.08 arc(261.51,22.24) 261.79,22.3 261.81,22.3 arc(261.99,22.33) 262.16,22.4 262.2,22.43 arc(262.25,22.46) 262.29,22.51 262.67,22.89 arc(262.76,23.02) 262.79,23.18 262.79,30.55 arc(262.7,30.76) 262.49,30.85 D4.3 261.44,30.85 arc(261.25,30.93) 261.18,31.12 261.18,33.98 arc(261.3,34.62) 261.67,35.17 arc(262.53,36.46) 262.83,37.98 262.83,39.85 arc(262.83,39.89) 262.8,39.92 arc(262.78,39.95) 262.77,39.99 U2.17
MDI_2_P: length 21.3
  BOTTOM w0.127: P1.3 135.51,22 arc(135.55,22.16) 135.65,22.29 135.79,22.39 arc(136.07,22.74) 136.17,23.18 136.17,32.42 arc(136.08,32.66) 135.84,32.75 D2.1 134.88,32.75 arc(134.65,32.85) 134.56,33.08 134.56,33.98 arc(134.66,34.48) 134.94,34.9 arc(135.88,36.32) 136.22,37.98 136.22,39.85 arc(136.22,39.89) 136.25,39.92 arc(136.27,39.95) 136.28,39.99 U1.16
MDI_2_P_A: length 21.3
  BOTTOM w0.127: P2.3 262.51,22 arc(262.55,22.16) 262.65,22.29 262.79,22.39 arc(263.07,22.74) 263.17,23.18 263.17,32.42 arc(263.08,32.66) 262.84,32.75 D4.1 261.88,32.75 arc(261.65,32.85) 261.56,33.08 261.56,33.98 arc(261.66,34.48) 261.94,34.9 arc(262.88,36.32) 263.22,37.98 263.22,39.85 arc(263.22,39.89) 263.25,39.92 arc(263.27,39.95) 263.28,39.99 U2.16
MDI_3_N: length 22.6
  BOTTOM w0.127: U1.19 134.77,39.99 arc(134.78,39.95) 134.8,39.92 arc(134.83,39.89) 134.83,39.85 134.83,38.13 arc(134.6,36.93) 133.92,35.92 arc(133.36,35.08) 133.16,34.09 133.16,33.07 arc(133.07,32.85) 132.84,32.75 D2.6 131.77,32.75 arc(131.55,32.66) 131.46,32.44 131.46,23.75 arc(131.75,23.05) 132.45,22.76 arc(133.34,22.94) 134.1,23.44 P1.9
MDI_3_N_A: length 22.6
  BOTTOM w0.127: U2.19 261.77,39.99 arc(261.78,39.95) 261.8,39.92 arc(261.83,39.89) 261.83,39.85 261.83,38.13 arc(261.6,36.93) 260.92,35.92 arc(260.36,35.08) 260.16,34.09 260.16,33.07 arc(260.07,32.85) 259.84,32.75 D4.6 258.77,32.75 arc(258.55,32.66) 258.46,32.44 258.46,23.75 arc(258.75,23.05) 259.45,22.76 arc(260.34,22.94) 261.1,23.44 P2.9
MDI_3_P: length 18.7
  BOTTOM w0.127: U1.18 135.28,39.99 arc(135.27,39.95) 135.25,39.92 arc(135.22,39.89) 135.22,39.85 135.22,38.13 arc(134.95,36.79) 134.19,35.65 arc(133.71,34.93) 133.54,34.09 133.54,31.11 arc(133.46,30.92) 133.28,30.85 D2.4 132.45,30.85 arc(132.02,30.67) 131.84,30.24 131.84,24.58 arc(131.86,24.47) 131.92,24.38 P1.8
MDI_3_P_A: length 18.7
  BOTTOM w0.127: P2.8 258.92,24.38 arc(258.86,24.47) 258.84,24.58 258.84,30.24 arc(259.02,30.67) 259.45,30.85 D4.4 260.28,30.85 arc(260.46,30.92) 260.54,31.11 260.54,34.09 arc(260.71,34.93) 261.19,35.65 arc(261.95,36.79) 262.22,38.13 262.22,39.85 arc(262.22,39.89) 262.25,39.92 arc(262.27,39.95) 262.28,39.99 U2.18
MLB_CLK_SOM_A: length 11.6
  TOP w0.127: SOMA.168 155.9,75.45 153.8,77.55 P38.1 DS1.A
MLB_CLK_SOM_B: length 11.6
  TOP w0.127: DS4.A P42.1 280.8,77.55 282.9,75.45 SOMB.168
MLB_DAT_SOM_A: length 11.6
  TOP w0.127: DS3.A P38.3 158.88,77.44 156.9,75.45 SOMA.172
MLB_DAT_SOM_B: length 11.6
  TOP w0.127: DS6.A P42.3 285.88,77.44 283.9,75.45 SOMB.172
MLB_SIG_SOM_A: length 10.8
  TOP w0.127: SOMA.170 156.39,78.05 P38.2 DS2.A
MLB_SIG_SOM_B: length 10.8
  TOP w0.127: DS5.A P42.2 283.39,78.05 SOMB.170
PB1_LED: length 67.8
  TOP w0.127: SOMA.105 v1(140.15,64.27)
  L3_SIG w0.127: v1(140.15,64.27) 140.15,67.57 139.09,68.62 139.09,70.33 140.11,71.35 146.52,71.35 149.59,68.28 168.58,68.28 181.25,80.95 187.63,80.95 v1(189.36,82.68)
  BOTTOM w0.127: U79.2 189.97,82.06 v1(189.36,82.68)
PB1_LED_X: length 2.5
  BOTTOM w0.127: R600.2 189.97,79.35 U79.10
PB2_LED: length 67.3
  TOP w0.127: SOMA.107 v1(140.64,64.78)
  L3_SIG w0.127: v1(140.64,64.78) 140.64,67.79 139.65,68.78 139.65,70.26 140.28,70.89 145.9,70.89 149.28,67.51 168.81,67.51 180.87,79.58 187.58,79.58 190.12,82.12 v1(190.12,82.68)
  BOTTOM w0.127: U79.3 190.37,82.42 v1(190.12,82.68)
PB2_LED_X: length 2.2
  BOTTOM w0.127: U79.9 190.37,78.61 R601.2
PB3_LED: length 87.6
  TOP w0.127: SOMB.105 v1(267.15,64.27)
  L3_SIG w0.127: v1(267.15,64.27) 267.15,65.31 264.98,67.48 225.89,67.48 221.74,71.63 215.14,71.63 211.37,75.4 198.29,75.4 191.55,82.13 191.54,82.13 191.22,82.45 191.22,82.46 v1(191.01,82.68)
  BOTTOM w0.127: v1(191.01,82.68) 190.77,82.44 U79.4
PB3_LED_X: length 2.2
  BOTTOM w0.127: U79.8 190.77,78.59 R602.2
PB4_LED: length 86.6
  TOP w0.127: SOMB.107 v1(267.64,64.78)
  L3_SIG w0.127: v1(267.64,64.78) 267.64,65.59 265.29,67.94 226.19,67.94 222.12,72.01 215.39,72.01 211.61,75.79 198.65,75.79 v1(191.77,82.68)
  BOTTOM w0.127: v1(191.77,82.68) 191.17,82.08 U79.5
PB4_LED_X: length 2.5
  BOTTOM w0.127: R603.2 191.17,79.33 U79.7
PUSHBUTTON_A_1: length 94
  TOP w0.127: SOMA.106 v1(140.39,70.19)
  L3_SIG w0.127: v1(218.5,43.16) 215.82,45.85 167.06,45.85 144.6,68.3 142.29,68.3 v1(140.39,70.19)
  BOTTOM w0.14: U7.3 v1(218.5,43.16)
PUSHBUTTON_A_2: length 92.5
  TOP w0.127: SOMA.108 140.9,70.57 v1(141.27,70.19)
  L3_SIG w0.127: v1(218.5,45.11) 217.28,46.33 167.26,46.33 144.78,68.81 142.66,68.81 v1(141.27,70.19)
  BOTTOM w0.14: U7.6 v1(218.5,45.11)
PUSHBUTTON_A_EN*: length 253.3
  TOP w0.127: v1(30.71,117.93) 30.73,117.91 U8.3
  L3_SIG w0.127: v1(215.14,44.96) 166.62,44.96 156.77,35.1 81.08,35.1 54.31,61.87 54.31,87.48 27.84,113.94 27.84,117.07 28.7,117.93 v1(30.71,117.93)
  BOTTOM w0.127: U7.1 R24.2 R25.1 U7.4
  BOTTOM w0.14: R25.1 215.64,44.46 v1(215.14,44.96)
PUSHBUTTON_B_1: length 77
  TOP w0.127: v1(237.95,51.23) 249.28,51.23 257.63,59.58 270.76,59.58 272.88,61.7 272.88,68.45 272.54,68.79 269.95,68.79 267.39,71.34 SOMB.106
  L8_SIG w0.127: v1(220.46,45.76) 225.93,51.23 v1(237.95,51.23)
  BOTTOM w0.14: U7.8 v1(220.46,45.76)
PUSHBUTTON_B_2: length 78.1
  TOP w0.127: SOMB.108 267.9,71.55 270.15,69.29 272.75,69.29 273.38,68.66 273.38,61.49 270.97,59.08 257.84,59.08 249.33,50.57 v1(237.95,50.57)
  L8_SIG w0.127: v1(237.95,50.57) 226.11,50.57 220.88,45.34 220.88,44.36 v1(221.42,43.81)
  BOTTOM w0.14: U7.11 v1(221.42,43.81)
PUSHBUTTON_B_EN*: length 119.3
  TOP w0.127: v1(258.93,123.55) 258.69,123.31 U51.3 ; v1(244.35,100.71) 244.35,87.93 241.88,85.47 237.87,85.47 236.91,84.51 236.91,80.06 235.71,78.87 225.55,78.87 223.52,76.83 223.52,65.91 219.58,61.98 v1(219.58,46.38)
  L3_SIG w0.127: v1(244.35,100.71) 244.35,114.63 254.28,124.56 257.91,124.56 v1(258.93,123.55)
  BOTTOM w0.127: U7.10 R22.1 R21.2 U7.13
  BOTTOM w0.14: v1(219.58,46.38) 223.54,46.38 224.29,45.63 R22.1
QSPI_CITO_SOM_A: length 10.3
  TOP w0.127: SOMA.94 v1(137.39,75.18)
  BOTTOM w0.127: R405.1 137.22,82.99 136.91,82.68 136.91,75.67 v1(137.39,75.18)
QSPI_CITO_SOM_A_A2B: length 160.6
  L8_SIG w0.127: v1(19.49,78.48) 19.49,77.69 15.6,73.79 10.9,73.79 9.25,72.14 9.25,70.1 10.62,68.73 45.62,68.73 47.5,70.61 65.12,70.61 65.62,71.12 v1(72.19,71.12) 77.95,71.12 80.56,68.51 110.09,68.51 112.09,70.51 120.44,70.51 122.7,72.77 130.37,72.77 137.03,79.43 138.96,79.43 139.67,80.15 139.67,81.31 v1(140.84,82.47)
  BOTTOM w0.127: J5.64 72.2,71.13 v1(72.19,71.12) ; J4.63 v1(19.49,78.48) ; U46.6 v1(140.84,82.47)
QSPI_CITO_SOM_B: length 153
  TOP w0.127: SOMB.94 v1(264.39,75.18)
  L3_SIG w0.127: v1(264.39,75.18) 264.39,74.22 271.41,67.21 301.3,67.21 304.04,64.47 315.19,64.47 322.35,57.3 338.22,57.3 356.62,57.3 360.81,53.11 369.9,53.11 v1(387.54,70.76)
  BOTTOM w0.127: R417.2 264.22,82.99 263.91,82.68 263.91,75.67 v1(264.39,75.18) ; P4.64 v1(387.54,70.76)
QSPI_CITO_SOM_B_A2B: length 74.7
  L3_SIG w0.127: v1(334.84,79.65) 319.58,79.65 316.41,76.48 284.56,76.48 282.73,78.31 272.31,78.31 271.15,79.48 270.28,79.48 268.88,80.87 268.88,81.43 v1(267.84,82.47)
  BOTTOM w0.127: U48.6 v1(267.84,82.47) ; P3.63 v1(334.84,79.65)
QSPI_CLK_SOM_A: length 8.3
  TOP w0.127: SOMA.92 136.9,75.43 v1(137.41,75.95)
  BOTTOM w0.127: v1(137.41,75.95) 137.41,81.21 R404.1
QSPI_CLK_SOM_A_A2B: length 163.3
  L8_SIG w0.127: v1(16.95,78.48) 16.95,77.64 14.17,74.85 10.45,74.85 8.33,72.73 8.33,69.64 10.32,67.65 45.23,67.65 47.19,65.68 52.37,65.68 56.24,69.55 66.5,69.55 66.98,70.03 v1(69.66,70.03) 77.5,70.03 79.78,67.74 110.87,67.74 112.9,69.77 120.71,69.77 123,72.06 130.7,72.06 137.36,78.72 139.8,78.72 140.84,79.75 v1(140.84,80.97)
  BOTTOM w0.127: U46.3 v1(140.84,80.97) ; J4.71 v1(16.95,78.48) ; J5.72 v1(69.66,70.03)
QSPI_CLK_SOM_B: length 158.6
  TOP w0.127: SOMB.92 263.9,75.43 v1(264.41,75.95)
  L3_SIG w0.127: v1(385,71.72) 385.4,71.32 387.81,71.32 388.09,71.04 388.09,70.51 368.14,50.57 362.56,50.57 356.26,56.87 322.17,56.87 315.01,64.03 303.86,64.03 301.09,66.8 271.27,66.8 263.55,74.52 263.55,75.56 263.93,75.95 v1(264.41,75.95)
  BOTTOM w0.127: v1(264.41,75.95) 264.41,81.21 R416.2 ; P4.72 v1(385,71.72)
QSPI_CLK_SOM_B_A2B: length 70.7
  L3_SIG w0.127: v1(267.84,80.97) 270.91,77.9 282.5,77.9 284.28,76.12 316.76,76.12 319.71,79.07 v1(332.3,79.07)
  BOTTOM w0.127: U48.3 v1(267.84,80.97) ; P3.71 v1(332.3,79.07)
QSPI_COTI_SOM_A: length 19
  TOP w0.127: v1(138.39,76.58) 137.9,76.08 SOMA.96
  BOTTOM w0.127: R406.1 147.83,81.72 147.83,78.99 146.18,77.34 139.16,77.34 v1(138.39,76.58)
QSPI_COTI_SOM_A_A2B: length 163.8
  L8_SIG w0.127: v1(142.88,82.97) 141.67,81.76 140.77,81.76 140.13,81.13 140.13,79.77 139.44,79.07 137.18,79.07 130.52,72.42 122.85,72.42 120.56,70.13 112.49,70.13 110.49,68.14 80.16,68.14 77.72,70.57 v1(70.93,70.57) 66.92,70.57 66.34,70 55.12,70 53.29,68.17 10.49,68.17 8.82,69.84 8.82,72.53 10.66,74.36 14.82,74.36 18.22,77.76 v1(18.22,78.48)
  BOTTOM w0.127: J4.67 v1(18.22,78.48) ; U46.10 v1(142.88,82.97) ; J5.68 v1(70.93,70.57)
QSPI_COTI_SOM_B: length 159.3
  TOP w0.127: v1(265.39,76.58) 264.9,76.08 SOMB.96
  L3_SIG w0.127: v1(265.39,76.58) 265.39,76.16 266.5,75.06 266.5,72.69 271.63,67.56 301.44,67.56 304.19,64.82 315.34,64.82 322.5,57.66 357.05,57.66 359.16,55.55 371.47,55.55 383.16,67.24 383.16,67.65 v1(386.27,70.76)
  BOTTOM w0.127: v1(265.39,76.58) 265.9,77.09 272.92,77.09 274.83,78.99 274.83,81.72 R418.2 ; P4.68 v1(386.27,70.76)
QSPI_COTI_SOM_B_A2B: length 73.7
  L3_SIG w0.127: v1(333.57,80.82) 319.28,80.82 315.67,77.22 285.29,77.22 281.46,81.05 273.57,81.05 272.7,80.19 271.48,80.19 270.43,81.23 270.43,82.42 v1(269.88,82.97)
  BOTTOM w0.127: U48.10 v1(269.88,82.97) ; P3.67 v1(333.57,80.82)
QSPI_D2_SOM_A: length 35.1
  TOP w0.127: SOMA.98 v1(138.39,75.38)
  BOTTOM w0.127: v1(138.39,75.38) 137.57,74.55 137.16,74.55 136.4,75.31 136.4,83.06 139.06,85.72 139.06,91.06 137.41,92.71 129.79,92.71 128.91,91.82 128.91,90.24 R520.1
QSPI_D2_SOM_B: length 35
  TOP w0.127: SOMB.98 v1(265.39,75.38)
  BOTTOM w0.127: v1(265.39,75.38) 264.67,74.65 264.06,74.65 263.4,75.31 263.4,83.06 266.06,85.72 266.06,91.06 264.41,92.71 256.79,92.71 255.91,91.82 255.91,90.24 R526.2
QSPI_D3_SOM_A: length 32.3
  TOP w0.127: SOMA.100 v1(138.9,74.87)
  BOTTOM w0.127: R521.1 129.55,91.7 130.16,92.31 137.07,92.31 138.56,90.82 138.56,85.98 135.92,83.34 135.92,75.16 136.91,74.17 138.19,74.17 v1(138.9,74.87)
QSPI_D3_SOM_B: length 32.2
  TOP w0.127: SOMB.100 v1(265.9,74.87)
  BOTTOM w0.127: v1(265.9,74.87) 265.27,74.24 263.83,74.24 262.92,75.16 262.92,83.34 265.56,85.98 265.56,90.82 264.07,92.31 257.16,92.31 256.55,91.7 R527.2
QSPI_ROUTE: length 289.8
  TOP w0.127: R513.1 v1(26.67,110.93) 27.25,111.51 29.08,111.51 29.23,111.65 U8.13
  L3_SIG w0.127: v1(265.73,79.97) 266.49,79.97 266.75,80.24 266.75,83.13 264.26,85.62 260.59,85.62 v1(258.11,88.1) 257.12,88.1 255.2,86.18 247.65,86.18 240.38,78.92 224.56,78.92 214.9,88.58 203.78,88.58 202.41,87.21 201.91,87.21 200.34,88.77 187.15,88.77 184.43,86.06 157.18,86.06 153.26,82.14 146.3,82.14 144.78,80.62 144.35,80.62 144.05,80.91 144.05,83.15 142.57,84.63 139.83,84.63 138.46,83.26 138.46,80.31 v1(138.18,80.04) 137.36,80.04 131.48,85.92 131.48,87.73 v1(131.11,88.1)
  L8_SIG w0.127: v1(26.67,110.93) 27.86,110.93 28.08,110.72 57.18,110.72 66.78,101.12 106.15,101.12 110.36,96.9 110.36,95.69 113.14,92.91 119.56,92.91 122.68,89.79 129.42,89.79 v1(131.11,88.1)
  BOTTOM w0.127: U48.1 v1(265.73,79.97) ; U62.1 v1(258.11,88.1) ; U61.1 v1(131.11,88.1) ; U46.1 138.24,79.97 v1(138.18,80.04) ; R513.1 v1(26.67,110.93)
QSPI_SEL1_SOM_A: length 19.6
  TOP w0.127: SOMA.102 v1(139.39,76.58)
  BOTTOM w0.127: v1(139.39,76.58) 138.89,76.07 138.18,76.07 137.93,76.32 137.93,76.96 138.81,77.85 145.97,77.85 147.32,79.2 147.32,81.41 146.75,81.98 R407.1
QSPI_SEL1_SOM_A_A2B: length 167.6
  L8_SIG w0.127: v1(142.88,81.47) 142.88,80.83 140.41,78.36 137.54,78.36 130.89,71.7 123.14,71.7 120.86,69.42 113.41,69.42 111.35,67.36 79.4,67.36 77.65,69.11 v1(67.12,69.11) 60.1,69.11 54.15,63.17 47.78,63.17 43.66,67.29 10,67.29 7.85,69.44 7.85,72.93 10.25,75.34 13.25,75.34 15.68,77.77 v1(15.68,78.48)
  BOTTOM w0.127: J4.75 v1(15.68,78.48) ; U46.13 v1(142.88,81.47) ; J5.80 v1(67.12,69.11)
QSPI_SEL1_SOM_B: length 155.2
  TOP w0.127: SOMB.102 v1(266.39,76.58)
  L3_SIG w0.127: v1(382.46,71.72) 382.46,67.43 373.05,58.01 322.67,58.01 315.43,65.25 304.42,65.25 301.75,67.92 272.01,67.92 267.59,72.34 267.59,75.95 266.95,76.58 v1(266.39,76.58)
  BOTTOM w0.127: v1(266.39,76.58) 265.89,76.07 265.18,76.07 264.93,76.32 264.93,76.96 265.56,77.6 272.71,77.6 274.32,79.2 274.32,81.41 273.75,81.98 R419.2 ; P4.80 v1(382.46,71.72)
QSPI_SEL1_SOM_B_A2B: length 68.9
  L3_SIG w0.127: v1(331.03,80.2) 319.29,80.2 315.93,76.83 285.01,76.83 283.11,78.74 274.37,78.74 273.28,79.83 270.89,79.83 269.88,80.84 v1(269.88,81.47)
  BOTTOM w0.127: P3.75 v1(331.03,80.2) ; U48.13 v1(269.88,81.47)
QSPI_SEL2_SOM_A: length 166.5
  TOP w0.127: SOMA.104 v1(139.9,75.45)
  L8_SIG w0.127: v1(139.9,75.45) 139.9,74.29 136.96,71.35 123.29,71.35 121,69.06 113.87,69.06 111.73,66.93 79.04,66.93 77.42,68.55 v1(68.39,68.55) 60.53,68.55 52.58,60.6 45.19,60.6 38.86,66.93 9.63,66.93 7.34,69.23 7.34,73.14 10.04,75.84 13.03,75.84 14.41,77.23 v1(14.41,78.48)
  BOTTOM w0.127: J4.79 v1(14.41,78.48) ; J5.76 v1(68.39,68.55)
QSPI_SEL2_SOM_B: length 134.7
  TOP w0.127: SOMB.104 v1(266.9,75.45)
  L8_SIG w0.127: v1(266.9,75.45) 269.83,78.38 294.23,78.38 300.48,72.14 300.49,72.14 301.07,71.56 312.46,71.56 313.03,72.14 319.71,72.14 v1(320.29,71.55) ; v1(329.76,78.48) 329.76,78.02 330.36,77.42 357.96,77.42 359.56,75.82 370.79,75.82 373.41,73.2 382.81,73.2 383.73,72.28 v1(383.73,71.72)
  BOTTOM w0.127: v1(320.29,71.55) 320.29,74.75 320.95,75.41 329.46,75.41 329.76,75.7 P3.79 v1(329.76,78.48) ; P4.76 v1(383.73,71.72)
REG_EN: length 487.4
  TOP w0.305: U49.10 v1(401.52,155.28) 401.52,156.04 R440.1 ; U50.10 v1(401.52,109.69) ; U4.10 v1(401.52,175.73) ; P17.2 R459.2 ; U3.10 v1(401.52,132.55)
  L3_SIG w0.127: v1(227.38,53.51) v1(227.38,61.05)
  L8_SIG w0.127: P17.2 386.51,171.45 390.79,175.73 v1(401.52,175.73) v1(401.52,155.28) v1(401.52,132.55) v1(401.52,109.69) 401.52,85.67 397.76,81.91 397.76,59.46 374.62,36.32 363.35,36.32 352.82,46.85 288.94,46.85 277.11,58.67 255.4,58.67 249.43,52.7 228.19,52.7 v1(227.38,53.51) 224.2,53.51 223.39,52.7 196.93,52.7 191.44,58.19 122.91,58.19 120.06,61.05 v1(100.38,61.05)
  BOTTOM w0.305: U78.10 v1(227.38,61.05) ; U77.10 v1(100.38,61.05)
SPDIF1_COAX_EN*: length 121.2
  TOP w0.127: U8.1 v1(31.73,118.49)
  TOP w0.14: v1(14.35,26.92) 13.05,25.62 U74.13 ; U74.4 v1(15.45,26.92)
  L8_SIG w0.127: v1(31.73,118.49) 23.03,118.49 18.21,113.67 18.21,102.29 4.32,88.39 4.32,64.94 14.5,54.76 14.5,27.86 v1(15.45,26.92)
  BOTTOM w0.14: v1(14.35,26.92) 14.36,26.92 v1(15.45,26.92)
SPDIF1_EN*: length 105
  TOP w0.127: U8.7 v1(28.48,116.2)
  L8_SIG w0.127: v1(17.36,33.12) 17.36,53.38 5.46,65.28 5.46,87.5 18.92,100.97 18.92,113.38 23.4,117.86 26.83,117.86 v1(28.48,116.2)
  BOTTOM w0.14: U67.1 v1(17.36,33.12)
SPDIF1_IN_COAX: length 28.4
  TOP w0.127: U70.7 v1(36.7,25.15)
  TOP w0.14: U63.9 v1(14.35,20.32)
  BOTTOM w0.127: v1(36.7,25.15) 29.46,25.15 26.29,21.97 16,21.97 v1(14.35,20.32)
SPDIF1_IN_OPT: length 11.5
  TOP w0.127: U63.10 14.75,20.58 15.52,19.82 15.52,11.89 M1.3
SPDIF1_OPT_EN*: length 123.1
  TOP w0.127: U8.2 v1(31.23,119.13)
  TOP w0.14: U74.10 v1(12.71,27.57) ; U74.1 15.31,24.97 v1(14.74,25.54)
  L8_SIG w0.127: v1(31.23,119.13) 22.35,119.13 17.4,114.17 17.4,102.74 3.56,88.9 3.56,63.88 13.92,53.52 13.92,28.15 13.34,27.57 v1(12.71,27.57)
  BOTTOM w0.14: v1(14.74,25.54) v1(12.71,27.57)
SPDIF1_OUT_COAX: length 21.3
  TOP w0.127: U71.2 U71.1 v1(29.14,25.5)
  TOP w0.14: U63.7 13.55,21.41 13.35,21.21 v1(12.83,21.21)
  BOTTOM w0.127: v1(29.14,25.5) 26,22.35 13.97,22.35 v1(12.83,21.21)
SPDIF1_OUT_OPT: length 6.8
  TOP w0.127: M1.4 11.43,18.29 13.95,20.81 U63.8
SPDIF2_COAX_EN*: length 237.1
  TOP w0.127: U51.1 259.69,122.03 v1(260.07,122.4)
  TOP w0.14: U75.13 380.71,25.62 v1(382.02,26.92) ; U75.4 v1(383.11,26.92)
  L3_SIG w0.127: v1(383.11,26.92) 384.22,26.92 397.64,40.33 397.64,83.67 384.25,97.05 323.59,97.05 318.08,102.56 318.08,113.92 303.33,128.68 296.37,128.68 293.4,125.7 293.27,125.7 290.91,123.34 290.91,122.58 290.45,122.12 260.35,122.12 v1(260.07,122.4)
  BOTTOM w0.14: v1(382.02,26.92) 382.02,26.92 v1(383.11,26.92)
SPDIF2_EN*: length 224.5
  TOP w0.127: U51.7 v1(256.45,121.28)
  L3_SIG w0.127: v1(385.02,33.12) 395.15,43.25 395.15,84.79 383.97,95.96 323.67,95.96 317.37,102.26 317.37,113.62 303.03,127.97 296.67,127.97 291.64,122.94 291.64,122.17 290.75,121.28 v1(256.45,121.28)
  BOTTOM w0.14: U69.1 v1(385.02,33.12)
SPDIF2_IN_COAX: length 28.4
  TOP w0.127: U72.7 v1(404.37,25.15)
  TOP w0.14: U68.9 v1(382.02,20.32)
  BOTTOM w0.127: v1(382.02,20.32) 383.67,21.97 393.95,21.97 397.13,25.15 v1(404.37,25.15)
SPDIF2_IN_OPT: length 11.5
  TOP w0.127: U68.10 382.42,20.58 383.18,19.82 383.18,11.89 M2.3
SPDIF2_OPT_EN*: length 238.9
  TOP w0.127: v1(259.46,122.91) 259.2,122.64 U51.2
  TOP w0.14: U75.1 382.98,24.97 v1(382.41,25.54) ; U75.10 v1(380.38,27.57)
  L3_SIG w0.127: v1(259.46,122.91) 259.46,122.13 259.93,121.67 290.63,121.67 291.29,122.33 291.29,123.09 296.52,128.32 303.18,128.32 317.73,113.77 317.73,102.41 323.59,96.55 384.18,96.55 396.44,84.28 396.44,41.94 385.24,30.73 384.57,30.73 381.4,27.57 v1(380.38,27.57)
  BOTTOM w0.14: v1(382.41,25.54) v1(380.38,27.57)
SPDIF2_OUT_COAX: length 21.3
  TOP w0.127: U73.2 U73.1 v1(396.81,25.5)
  TOP w0.14: v1(380.49,21.21) 381.01,21.21 381.22,21.41 U68.7
  BOTTOM w0.127: v1(396.81,25.5) 393.66,22.35 381.63,22.35 v1(380.49,21.21)
SPDIF2_OUT_OPT: length 6.8
  TOP w0.127: U68.8 381.62,20.81 379.1,18.29 M2.4
SPI_CITO_SOM_A: length 188.5
  TOP w0.127: P30.7 v1(69.47,90.18) ; SOMA.114 v1(142.39,76.22) ; P32.4 16.03,82.7 14.25,82.7 13.23,81.69 13.23,76.46 16.39,73.3 18.37,73.3 19.49,72.18 v1(19.49,71.72)
  L8_SIG w0.127: v1(19.49,71.72) 20.12,71.09 39.06,71.09 43.59,75.62 43.59,79.65 47.22,83.29 54.76,83.29 55.37,82.68 67.95,82.68 v1(69.09,81.53) 69.8,81.53 71.15,80.19 98.32,80.19 100.61,82.48 111.92,82.48 115.6,86.17 127.6,86.17 128.17,85.6 143.89,85.6 145.9,83.59 145.9,80.38 145.03,79.52 145.03,77.98 143.27,76.22 v1(142.39,76.22)
  BOTTOM w0.127: J5.63 72.2,79.31 69.98,81.53 v1(69.09,81.53) 68.83,81.79 68.83,89.55 v1(69.47,90.18) ; J4.64 v1(19.49,71.72)
SPI_CITO_SOM_B: length 183
  TOP w0.127: P31.7 v1(384.81,90.18) ; SOMB.114 v1(269.39,74.95) ; v1(334.84,69.29) 334.84,72.18 333.72,73.3 331.73,73.3 328.57,76.46 328.57,81.69 329.59,82.7 331.37,82.7 P33.4
  L3_SIG w0.127: v1(334.84,69.29) 338.47,65.66 370.69,65.66 378.71,73.69 385.62,73.69 387.54,75.6 v1(387.54,78.48)
  L8_SIG w0.127: v1(334.84,69.29) 334.84,63.81 332.01,60.98 319.04,60.98 317.3,62.71 283.24,62.71 280.63,65.32 279.48,65.32 275.31,69.49 272.94,69.49 269.39,73.04 v1(269.39,74.95)
  BOTTOM w0.127: P4.63 v1(387.54,78.48) 387.54,85.41 384.81,88.14 v1(384.81,90.18) ; P3.64 v1(334.84,69.29)
SPI_CLK_SOM_A: length 189
  TOP w0.127: SOMA.112 v1(141.9,76.72) ; P30.9 v1(68.2,90.18) ; v1(16.95,71.72) 16.95,72.18 16.55,72.59 16.09,72.59 12.52,76.15 12.52,82.5 13.23,83.21 13.23,84.23 13.97,84.96 18.54,84.96 P32.2
  L8_SIG w0.127: v1(16.95,71.72) 18.6,70.08 39.48,70.08 47.73,78.33 54.46,78.33 57.79,81.66 66.9,81.66 68.17,80.39 v1(68.2,80.39) 68.2,80.37 69.09,79.48 98.66,79.48 100.92,81.74 112.23,81.74 115.91,85.42 127.29,85.42 127.86,84.85 143.58,84.85 145.15,83.28 145.15,80.64 144.32,79.81 144.32,78.66 143.13,77.47 142.64,77.47 v1(141.9,76.72)
  BOTTOM w0.127: J5.71 69.66,78.91 68.2,80.37 v1(68.2,80.39) v1(68.2,90.18) ; J4.72 v1(16.95,71.72)
SPI_CLK_SOM_B: length 185.8
  TOP w0.127: SOMB.112 v1(268.9,75.45) ; P31.9 v1(383.54,90.18) ; v1(332.3,71.72) 332.3,72.18 331.89,72.59 331.43,72.59 327.86,76.15 327.86,82.5 328.57,83.21 328.57,84.23 329.31,84.96 333.88,84.96 P33.2
  L3_SIG w0.127: v1(385,78.48) 385.01,78.47 385.01,76.45 384.35,75.79 378.33,75.79 373.25,70.71 360.83,70.71 360.53,71.02 333,71.02 v1(332.3,71.72)
  L8_SIG w0.127: v1(332.3,71.72) 332.77,71.25 335.03,71.25 335.41,70.87 335.41,63.88 332.15,60.62 318.89,60.62 317.26,62.26 281.89,62.26 275.03,69.12 272.61,69.12 268.9,72.84 v1(268.9,75.45)
  BOTTOM w0.127: P3.72 v1(332.3,71.72) ; P4.71 v1(385,78.48) 385,79.69 385.6,80.29 385.6,85.65 385.28,85.97 385.28,86.31 385,86.59 384.56,86.59 383.54,87.61 v1(383.54,90.18)
SPI_COTI_SOM_A: length 174.7
  TOP w0.127: v1(69.34,80.14) 68.2,81.28 P30.10 ; SOMA.116 v1(142.9,76.72) ; P32.6 12.88,82.09 12.88,76.31 16.24,72.94 17.46,72.94 18.22,72.18 v1(18.22,71.72)
  L8_SIG w0.127: v1(142.9,76.72) 142.9,76.73 144.68,78.51 144.68,79.67 145.54,80.53 145.54,83.44 143.74,85.24 128.03,85.24 127.46,85.81 115.75,85.81 112.07,82.13 100.76,82.13 98.47,79.83 69.65,79.83 v1(69.34,80.14) 67.44,82.04 55.37,82.04 54.38,81.05 47.85,81.05 44.09,77.29 44.09,75.44 39.26,70.61 19.33,70.61 v1(18.22,71.72)
  BOTTOM w0.127: J5.67 70.93,78.55 v1(69.34,80.14) ; J4.68 v1(18.22,71.72)
SPI_COTI_SOM_B: length 170
  TOP w0.127: v1(333.57,70.23) 333.57,72.18 332.8,72.94 331.58,72.94 328.22,76.31 328.22,82.09 P33.6 ; SOMB.116 v1(269.9,75.45) ; v1(386.27,78.48) 383.54,81.21 P31.10
  L3_SIG w0.127: v1(386.27,78.48) 386.27,76.13 385.1,74.96 378.92,74.96 372.01,68.05 363.14,68.05 362.02,66.93 338.58,66.93 335.28,70.23 v1(333.57,70.23)
  L8_SIG w0.127: v1(333.57,70.23) 333.57,69.15 334.14,68.58 334.14,63.61 331.94,61.42 319.1,61.42 317.45,63.07 283.39,63.07 276.61,69.85 273.3,69.85 269.9,73.25 v1(269.9,75.45)
  BOTTOM w0.127: P4.67 v1(386.27,78.48) ; P3.68 v1(333.57,70.23)
SPI_RDY_SOM_A: length 169.4
  TOP w0.14: SOMA.122 v1(144.39,75.96)
  L8_SIG w0.127: P32.12 6.2,83.03 6.2,69.24 8.86,66.58 38.32,66.58 46.86,58.04 54.99,58.04 64.87,67.92 77.24,67.92 78.59,66.57 112.14,66.57 114.27,68.71 121.15,68.71 123.34,70.89 137.24,70.89 140.18,73.84 143.4,73.84 144.39,74.84 v1(144.39,75.96)
SPI_RDY_SOM_B: length 72.4
  TOP w0.127: P33.12 320.98,82.47 v1(320.98,70.23) ; SOMB.122 v1(271.39,74.95)
  L8_SIG w0.127: v1(320.98,70.23) 318.39,67.64 304.22,67.64 293.88,77.98 273.33,77.98 271.39,76.04 v1(271.39,74.95)
SPI_SEL1_SOM_A: length 168.5
  TOP w0.127: P32.8 12.06,82.3 12.17,82.19 12.17,76 15.68,72.48 v1(15.68,71.72) ; SOMA.118 v1(143.39,75.44)
  L8_SIG w0.127: v1(15.68,71.72) 17.76,69.65 39.66,69.65 45.86,75.84 52.86,75.84 58.04,81.03 65.85,81.03 v1(67.12,79.76) 68.04,79.76 68.7,79.1 98.79,79.1 101.07,81.38 112.37,81.38 116.06,85.06 127.15,85.06 127.72,84.5 143.26,84.5 144.02,83.73 144.02,80.08 141.33,77.39 141.33,76.53 142.43,75.44 v1(143.39,75.44)
  BOTTOM w0.127: J5.79 v1(67.12,79.76) ; J4.76 v1(15.68,71.72)
SPI_SEL1_SOM_B: length 153
  TOP w0.127: SOMB.118 v1(270.39,74.95) ; P33.8 327.41,82.3 327.51,82.19 327.51,76 331.03,72.48 v1(331.03,71.72)
  L3_SIG w0.127: v1(331.03,71.72) 331.03,72.3 331.42,72.69 361.75,72.69 362.31,73.25 372.62,73.25 375.92,76.56 381.89,76.56 382.45,77.11 382.45,78.47 v1(382.46,78.48)
  L8_SIG w0.127: v1(270.39,74.95) 270.39,73.46 273.65,70.2 276.95,70.2 283.73,63.42 317.6,63.42 319.23,61.79 331.81,61.79 333.5,63.48 333.5,67.7 331.03,70.17 v1(331.03,71.72)
  BOTTOM w0.127: P4.79 v1(382.46,78.48) ; P3.76 v1(331.03,71.72)
SPI_SEL2_SOM_A: length 183.6
  TOP w0.127: P32.10 11.79,81.56 11.79,75.88 14.41,73.25 v1(14.41,71.72) ; SOMA.120 v1(143.9,74.95) ; P30.11 v1(66.93,90.18)
  L8_SIG w0.127: v1(14.41,71.72) 16.9,69.24 39.83,69.24 43.87,73.28 53.04,73.28 60.15,80.39 65.15,80.39 66.42,79.12 v1(67.82,79.12) 68.2,78.74 98.93,78.74 101.22,81.03 112.52,81.03 116.2,84.71 122.15,84.71 127,84.71 127.57,84.14 143.11,84.14 143.64,83.61 143.64,80.39 140.84,77.6 140.84,76.33 142.22,74.95 v1(143.9,74.95)
  BOTTOM w0.127: v1(66.93,90.18) 67.49,89.62 67.49,80.33 67.82,80 v1(67.82,79.12) 68.39,78.55 J5.75 ; J4.80 v1(14.41,71.72)
SPI_SEL2_SOM_B: length 170.5
  TOP w0.127: v1(329.76,71.72) 329.76,73.25 327.13,75.88 327.13,81.56 P33.10 ; SOMB.120 v1(270.9,75.45) ; P31.11 v1(382.27,90.18)
  L3_SIG w0.127: v1(329.76,71.72) 329.76,72.45 330.45,73.15 359.74,73.15 362.38,75.79 373.35,75.79 374.88,77.32 379.86,77.32 381.66,79.12 383.09,79.12 v1(383.73,78.48)
  L8_SIG w0.127: v1(329.76,71.72) 329.76,70.42 332.99,67.18 332.99,63.47 331.67,62.15 319.38,62.15 317.74,63.78 298.3,63.78 292.89,69.19 278.82,69.19 277.39,70.61 273.95,70.61 270.9,73.66 v1(270.9,75.45)
  BOTTOM w0.127: P4.75 v1(383.73,78.48) 383.73,80.96 384.28,81.52 384.28,85.07 382.27,87.09 v1(382.27,90.18) ; P3.80 v1(329.76,71.72)
SYS_HWRST*: length 579.1
  TOP w0.127: R515.2 v1(72.83,80.78) ; R518.2 v1(388.18,80.78) ; R587.2 v1(309.4,78.99) ; R586.2 v1(182.37,78.94) ; v1(233.46,25.7) 233.11,25.35 231.32,25.35 228.22,28.45 R552.2 ; v1(35.76,109.25) 35.76,110.85 35.17,111.43 R31.2 33.53,112.2 33.53,113.16 33.2,113.49 U8.20 ; U51.20 261.16,118.57 261.49,118.24 261.49,117.28 R32.2 v1(263.27,116.51) ; U66.8 234.33,27.37 234.19,27.23 234.19,26.77 234.06,26.64 233.64,26.64 R551.2
  TOP w0.14: R551.2 v1(233.46,25.7) ; v1(101.89,83.59) v1(101.89,86.59)
  L3_SIG w0.114: v1(101.89,86.59) v1(101.89,83.59)
  L3_SIG w0.127: v1(388.18,80.78) 386.25,82.7 376.15,82.7 374.5,81.05 342.37,81.05 335.53,87.88 321.56,87.88 312.67,78.99 v1(309.4,78.99) 308.89,79.5 308.89,82.88 313.31,87.3 313.31,104.57 309.5,108.38 271.4,108.38 v1(263.27,116.51) 251.57,116.51 247.4,112.34 247.4,101.88 245.39,99.87 243.93,99.87 236.85,106.95 236.85,107.57 235.46,108.97 201.68,108.97 v1(200.94,109.7) ; v1(233.46,25.7) 231.34,25.7 223.01,34.04 223.01,44.7 216.66,51.05 210.26,51.05 v1(182.37,78.94)
  L8_SIG w0.127: v1(101.89,83.59) 101.13,83.59 99.41,81.86 99.39,81.86 98.31,80.78 v1(72.83,80.78) 71.58,82.04 71.58,93.65 55.98,109.25 v1(35.76,109.25) ; v1(101.89,86.59) 102.76,85.72 114.3,85.72 115.44,86.87 127.64,86.87 128.52,85.98 149.05,85.98 155.56,79.46 181.85,79.46 v1(182.37,78.94)
  BOTTOM w0.127: v1(182.37,78.94) 182.37,85.06 186.41,89.1 196.72,89.1 200.94,93.32 v1(200.94,109.7)
  BOTTOM w0.14: U65.A2 v1(101.89,86.59) ; U65.A4 v1(101.89,83.59)
